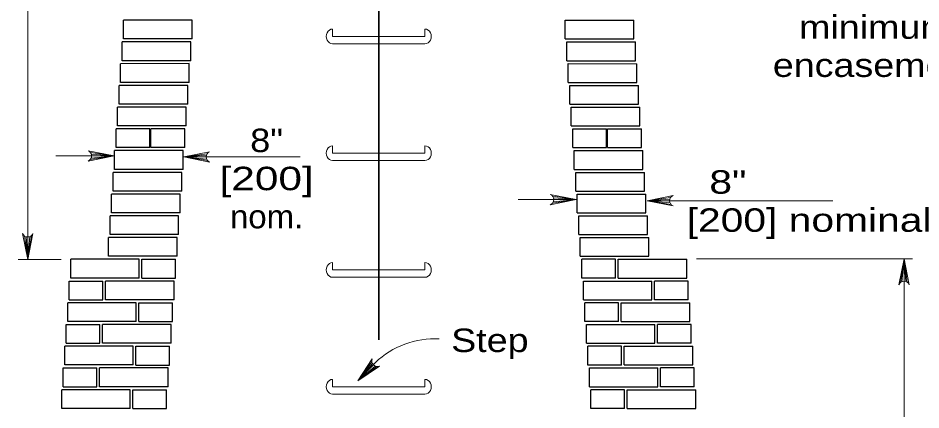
# Model space of a CAD drawing. Extents: x 750.7 to 784.7, y 860.1 to 882.1.
# Drawn here: x 753.86 to 760.02, y 869.85 to 872.53 of the extents above; entities that cross this region are included whole.
import ezdxf
from ezdxf.enums import TextEntityAlignment as Align

# ---------------------------------------------------------------- set-up
doc = ezdxf.new("R2010")
doc.units = 0
doc.header["$LTSCALE"] = 0.064
doc.layers.add('1', color=7, linetype='Continuous', lineweight=13)

msp = doc.modelspace()

# ---------------------------------------------------------------- linework, layer by layer
at = {"layer": '1', "lineweight": 35}
msp.add_line((756.31867, 870.33167), (756.31867, 877.19075), dxfattribs=at)
at = {"layer": '1'}
for p, q in [((753.92483, 870.88017), (753.92483, 873.18092)), ((756.00417, 872.40133), (756.00417, 872.4515)), ((756.63317, 872.40142), (756.63308, 872.4515)), ((756.00417, 872.40133), (756.63317, 872.40142)), ((756.00417, 872.35125), (756.63317, 872.35125)), ((756.00417, 871.60475), (756.00417, 871.65492)), ((756.63317, 871.60483), (756.63308, 871.65492)), ((754.11692, 871.58633), (754.51358, 871.58633)), ((754.35142, 871.5615), (754.51358, 871.58633)), ((754.35325, 871.60875), (754.51358, 871.58633)), ((754.3575, 871.57192), (754.51358, 871.58633)), ((754.35867, 871.59767), (754.51358, 871.58633)), ((754.36033, 871.58633), (754.51358, 871.58633)), ((755.14875, 871.6015), (754.98842, 871.57908)), ((755.14333, 871.59042), (754.98842, 871.57908)), ((754.98842, 871.57908), (755.78258, 871.57908)), ((755.14167, 871.57908), (754.98842, 871.57908)), ((755.1445, 871.56467), (754.98842, 871.57908)), ((755.15067, 871.55433), (754.98842, 871.57908)), ((756.00417, 871.60475), (756.63317, 871.60483)), ((756.00417, 871.55467), (756.63317, 871.55467)), ((757.26908, 871.2885), (757.66575, 871.2885)), ((757.50358, 871.26367), (757.66575, 871.2885)), ((757.50542, 871.31092), (757.66575, 871.2885)), ((757.50967, 871.27408), (757.66575, 871.2885)), ((757.51092, 871.29983), (757.66575, 871.2885)), ((757.5125, 871.2885), (757.66575, 871.2885)), ((758.30917, 871.30308), (758.14883, 871.28067)), ((758.30375, 871.292), (758.14883, 871.28067)), ((758.30208, 871.28067), (758.14883, 871.28067)), ((758.30492, 871.26625), (758.14883, 871.28067)), ((758.31108, 871.25592), (758.14883, 871.28067)), ((758.14883, 871.28067), (759.4165, 871.28067)), ((753.90242, 871.04042), (753.92483, 870.88017)), ((753.9135, 871.035), (753.92483, 870.88017)), ((753.94967, 871.04233), (753.92483, 870.88017)), ((753.93925, 871.03617), (753.92483, 870.88017)), ((753.92483, 871.03333), (753.92483, 870.88017)), ((754.15208, 870.88017), (753.85875, 870.88017)), ((756.00417, 870.80817), (756.00417, 870.85833)), ((756.63317, 870.80817), (756.63308, 870.85833)), ((758.48525, 870.88433), (759.95867, 870.88433)), ((759.87642, 870.72217), (759.90117, 870.88433)), ((759.88675, 870.72833), (759.90117, 870.88433)), ((759.90117, 870.73117), (759.90117, 870.88433)), ((759.9125, 870.7295), (759.90117, 870.88433)), ((759.92358, 870.72408), (759.90117, 870.88433)), ((759.90117, 865.26633), (759.90117, 870.88433)), ((756.00417, 870.80817), (756.63317, 870.80817)), ((756.00417, 870.75808), (756.63317, 870.75808)), ((756.73033, 870.33908), (756.702, 870.33908)), ((756.27142, 870.18108), (756.17533, 870.05083)), ((756.2755, 870.1695), (756.17533, 870.05083)), ((756.2825, 870.16033), (756.17533, 870.05083)), ((756.17533, 870.05083), (756.27408, 870.15508)), ((756.29475, 870.15233), (756.17533, 870.05083)), ((756.3065, 870.14942), (756.17533, 870.05083)), ((756.00417, 870.01158), (756.00417, 870.06175)), ((756.63317, 870.01158), (756.63308, 870.06175)), ((756.00417, 870.01158), (756.63317, 870.01158)), ((756.00417, 869.9615), (756.63317, 869.9615))]:
    msp.add_line(p, q, dxfattribs=at)
at = {"layer": '1', "lineweight": 25}
for p, q in [((754.52742, 871.64258), (754.52742, 871.77067)), ((754.765, 871.64258), (754.765, 871.77067)), ((757.87233, 871.64258), (757.87233, 871.77067)), ((758.10983, 871.64258), (758.10983, 871.77067)), ((754.75758, 871.64258), (754.52742, 871.64258)), ((754.99508, 871.64258), (754.765, 871.64258)), ((757.64217, 871.64258), (757.87233, 871.64258)), ((757.87975, 871.64258), (758.10983, 871.64258)), ((754.93358, 870.753), (754.93358, 870.88108)), ((757.70375, 870.753), (757.70375, 870.88108)), ((754.438, 870.60475), (754.438, 870.73283)), ((754.70342, 870.753), (754.93358, 870.753)), ((757.93383, 870.753), (757.70375, 870.753)), ((758.19925, 870.60475), (758.19925, 870.73283)), ((754.20792, 870.60475), (754.438, 870.60475)), ((754.91308, 870.4565), (754.91308, 870.5845)), ((757.72425, 870.4565), (757.72425, 870.5845)), ((758.42942, 870.60475), (758.19925, 870.60475)), ((754.4175, 870.30825), (754.4175, 870.43625)), ((754.68292, 870.4565), (754.91308, 870.4565)), ((757.95433, 870.4565), (757.72425, 870.4565)), ((758.21975, 870.30825), (758.21975, 870.43625)), ((754.18742, 870.30825), (754.4175, 870.30825)), ((754.89258, 870.15992), (754.89258, 870.288)), ((757.74475, 870.15992), (757.74475, 870.288)), ((758.44992, 870.30825), (758.21975, 870.30825)), ((754.66242, 870.15992), (754.89258, 870.15992)), ((757.97492, 870.15992), (757.74475, 870.15992)), ((754.397, 870.01167), (754.397, 870.13975)), ((758.24033, 870.01167), (758.24033, 870.13975)), ((754.16692, 870.01167), (754.397, 870.01167)), ((754.87208, 869.86342), (754.87208, 869.9915)), ((757.76525, 869.86342), (757.76525, 869.9915)), ((758.47042, 870.01167), (758.24033, 870.01167)), ((754.64192, 869.86342), (754.87208, 869.86342)), ((757.99542, 869.86342), (757.76525, 869.86342))]:
    msp.add_line(p, q, dxfattribs=at)
for points in [[(755.04642, 872.38392), (755.04642, 872.512), (754.57875, 872.512)], [(755.04642, 872.38392), (754.57875, 872.38392), (754.57875, 872.512)], [(757.59092, 872.38392), (757.59092, 872.512), (758.05858, 872.512)], [(757.59092, 872.38392), (758.05858, 872.38392), (758.05858, 872.512)], [(755.03617, 872.23567), (755.03617, 872.36375), (754.5685, 872.36375)], [(755.03617, 872.23567), (754.5685, 872.23567), (754.5685, 872.36375)], [(757.60117, 872.23567), (757.60117, 872.36375), (758.06883, 872.36375)], [(757.60117, 872.23567), (758.06883, 872.23567), (758.06883, 872.36375)], [(757.60117, 872.23567), (757.60117, 872.36375), (758.06883, 872.36375)], [(757.60117, 872.23567), (758.06883, 872.23567), (758.06883, 872.36375)], [(755.02592, 872.08742), (755.02592, 872.2155), (754.55825, 872.21542)], [(755.02592, 872.08742), (754.55825, 872.08742), (754.55825, 872.21542)], [(757.61142, 872.08742), (757.61142, 872.2155), (758.07908, 872.21542)], [(757.61142, 872.08742), (758.07908, 872.08742), (758.07908, 872.21542)], [(755.01567, 871.93917), (755.01567, 872.06717), (754.54792, 872.06717)], [(755.01567, 871.93917), (754.54792, 871.93917), (754.54792, 872.06717)], [(757.62167, 871.93917), (757.62167, 872.06717), (758.08933, 872.06717)], [(757.62167, 871.93917), (758.08933, 871.93917), (758.08933, 872.06717)], [(755.00542, 871.79083), (755.00542, 871.91892), (754.53767, 871.91892)], [(755.00542, 871.79083), (754.53767, 871.79083), (754.53767, 871.91892)], [(757.63192, 871.79083), (757.63192, 871.91892), (758.09958, 871.91892)], [(757.63192, 871.79083), (758.09958, 871.79083), (758.09958, 871.91892)], [(754.75758, 871.64258), (754.75758, 871.77067), (754.52742, 871.77067)], [(754.99508, 871.64258), (754.99508, 871.77067), (754.765, 871.77067)], [(757.64217, 871.64258), (757.64217, 871.77067), (757.87233, 871.77067)], [(757.87975, 871.64258), (757.87975, 871.77067), (758.10983, 871.77067)], [(754.98483, 871.49433), (754.98483, 871.62242), (754.51717, 871.62242)], [(754.98483, 871.49433), (754.51717, 871.49433), (754.51717, 871.62242)], [(757.65242, 871.49433), (757.65242, 871.62242), (758.12008, 871.62242)], [(757.65242, 871.49433), (758.12008, 871.49433), (758.12008, 871.62242)], [(754.97458, 871.34608), (754.97458, 871.47417), (754.50692, 871.47417)], [(754.97458, 871.34608), (754.50692, 871.34608), (754.50692, 871.47417)], [(757.66267, 871.34608), (757.66267, 871.47417), (758.13042, 871.47417)], [(757.66267, 871.34608), (758.13042, 871.34608), (758.13042, 871.47417)], [(754.96433, 871.19783), (754.96433, 871.32583), (754.49667, 871.32583)], [(754.96433, 871.19783), (754.49667, 871.19783), (754.49667, 871.32583)], [(757.67292, 871.19783), (757.67292, 871.32583), (758.14067, 871.32583)], [(757.67292, 871.19783), (758.14067, 871.19783), (758.14067, 871.32583)], [(754.95408, 871.04958), (754.95408, 871.17758), (754.48642, 871.17758)], [(754.95408, 871.04958), (754.48642, 871.04958), (754.48642, 871.17758)], [(757.68325, 871.0495), (757.68325, 871.17758), (758.15092, 871.17758)], [(757.68325, 871.0495), (758.15092, 871.04958), (758.15092, 871.17758)], [(754.94383, 870.90125), (754.94383, 871.02933), (754.47617, 871.02933)], [(754.94383, 870.90125), (754.47617, 870.90125), (754.47617, 871.02933)], [(757.6935, 870.90125), (757.6935, 871.02933), (758.16117, 871.02933)], [(757.6935, 870.90125), (758.16117, 870.90125), (758.16117, 871.02933)], [(754.68583, 870.753), (754.68583, 870.88108), (754.21817, 870.88108)], [(754.68583, 870.753), (754.21817, 870.753), (754.21817, 870.88108)], [(754.70342, 870.753), (754.70342, 870.88108), (754.93358, 870.88108)], [(757.93383, 870.753), (757.93383, 870.88108), (757.70375, 870.88108)], [(757.9515, 870.753), (757.9515, 870.88108), (758.41917, 870.88108)], [(757.9515, 870.753), (758.41917, 870.753), (758.41917, 870.88108)], [(754.20792, 870.60475), (754.20792, 870.73283), (754.438, 870.73283)], [(754.92333, 870.60475), (754.92333, 870.73283), (754.45567, 870.73283)], [(754.92333, 870.60475), (754.45567, 870.60475), (754.45567, 870.73283)], [(757.714, 870.60475), (757.714, 870.73283), (758.18167, 870.73283)], [(757.714, 870.60475), (758.18167, 870.60475), (758.18167, 870.73283)], [(758.42942, 870.60475), (758.42942, 870.73283), (758.19925, 870.73283)], [(754.66533, 870.4565), (754.66533, 870.58458), (754.19767, 870.58458)], [(754.66533, 870.4565), (754.19767, 870.4565), (754.19767, 870.58458)], [(754.68292, 870.4565), (754.68292, 870.5845), (754.91308, 870.5845)], [(757.95433, 870.4565), (757.95433, 870.5845), (757.72425, 870.5845)], [(757.972, 870.4565), (757.972, 870.58458), (758.43967, 870.58458)], [(757.972, 870.4565), (758.43967, 870.4565), (758.43967, 870.58458)], [(754.18742, 870.30825), (754.18742, 870.43625), (754.4175, 870.43625)], [(754.90283, 870.30825), (754.90283, 870.43625), (754.43517, 870.43625)], [(754.90283, 870.30825), (754.43517, 870.30825), (754.43517, 870.43625)], [(757.7345, 870.30825), (757.7345, 870.43625), (758.20217, 870.43625)], [(757.7345, 870.30825), (758.20217, 870.30825), (758.20217, 870.43625)], [(758.44992, 870.30825), (758.44992, 870.43625), (758.21975, 870.43625)], [(754.64483, 870.16), (754.64483, 870.288), (754.17717, 870.288)], [(754.64483, 870.16), (754.17717, 870.16), (754.17717, 870.288)], [(754.66242, 870.15992), (754.66242, 870.288), (754.89258, 870.288)], [(757.97492, 870.15992), (757.97492, 870.288), (757.74475, 870.288)], [(757.9925, 870.16), (757.9925, 870.288), (758.46017, 870.288)], [(757.9925, 870.16), (758.46017, 870.16), (758.46017, 870.288)], [(754.16692, 870.01167), (754.16692, 870.13975), (754.397, 870.13975)], [(754.88233, 870.01167), (754.88233, 870.13975), (754.41458, 870.13975)], [(754.88233, 870.01167), (754.41458, 870.01167), (754.41458, 870.13975)], [(757.755, 870.01167), (757.755, 870.13975), (758.22267, 870.13975)], [(757.755, 870.01167), (758.22267, 870.01167), (758.22267, 870.13975)], [(758.47042, 870.01167), (758.47042, 870.13975), (758.24033, 870.13975)], [(754.62433, 869.86342), (754.62433, 869.9915), (754.15658, 869.9915)], [(754.62433, 869.86342), (754.15658, 869.86342), (754.15658, 869.9915)], [(754.64192, 869.86342), (754.64192, 869.9915), (754.87208, 869.9915)], [(757.99542, 869.86342), (757.99542, 869.9915), (757.76525, 869.9915)], [(758.013, 869.86342), (758.013, 869.9915), (758.48067, 869.9915)], [(758.013, 869.86342), (758.48067, 869.86342), (758.48067, 869.9915)]]:
    msp.add_lwpolyline(points, dxfattribs=at)
at = {"layer": '1'}
for points in [[(754.3365, 871.55092), (754.51358, 871.58633), (754.3365, 871.62175)], [(755.1655, 871.54367), (754.98842, 871.57908), (755.1655, 871.6145)], [(757.48867, 871.25308), (757.66575, 871.2885), (757.48867, 871.32392)], [(758.32592, 871.24525), (758.14883, 871.28067), (758.32592, 871.31608)], [(753.96025, 871.05717), (753.92483, 870.88017), (753.88942, 871.05717)], [(759.86575, 870.70733), (759.90117, 870.88433), (759.93658, 870.70733)], [(756.3245, 870.15267), (756.17533, 870.05083), (756.27383, 870.20217)]]:
    msp.add_lwpolyline(points, dxfattribs=at)
for centre, radius, start, end in [((754.32221, 871.58634), 0.03822, 292.08605, 67.91218), ((755.17983, 871.57914), 0.03822, 112.08782, 247.91395), ((757.47439, 871.28853), 0.03822, 292.08605, 67.91218), ((758.34023, 871.2807), 0.03822, 112.08782, 247.91395), ((753.92481, 871.07151), 0.03822, 202.08782, 337.91395), ((759.90123, 870.693), 0.03822, 22.08782, 157.91395), ((756.70197, 869.7496), 0.58949, 90, 136.54123), ((756.30914, 870.18765), 0.03822, 157.70543, 293.53156)]:
    msp.add_arc(centre, radius, start, end, dxfattribs=at)
for centre, major_axis, end_param in [((756.00413, 872.40137), (0, 0.05012), 3.1415958), ((756.63317, 872.40137), (0, -0.05012), 3.143156), ((756.00413, 871.60479), (0, 0.05012), 3.1415958), ((756.63317, 871.60479), (0, -0.05012), 3.143156), ((756.00413, 870.80821), (0, 0.05012), 3.1415958), ((756.63317, 870.80821), (0, -0.05012), 3.143156), ((756.00413, 870.01162), (0, 0.05012), 3.1415958), ((756.63317, 870.01162), (0, -0.05012), 3.143156)]:
    msp.add_ellipse(centre, major_axis=major_axis, ratio=0.869565, start_param=0.000003, end_param=end_param, dxfattribs=at)

# ---------------------------------------------------------------- texts
for s, width, p in [('minimum', 1.2, (759.70558, 872.38492)), ('encasement', 1.2, (759.70558, 872.12492)), ('8"', 1.15, (755.55396, 871.61225)), ('[200]', 1.35, (755.55404, 871.35225)), ('nom.', 1.05, (755.554, 871.09225))]:
    msp.add_text(s, height=0.16, dxfattribs=dict(at, width=width)).set_placement(p, align=Align.CENTER)
for s, width, p in [('  8"', 1.3, (758.41875, 871.32858)), ('[200] nominal', 1.3, (758.41875, 871.06858)), ('Step', 1.2, (756.81242, 870.24833))]:
    msp.add_text(s, height=0.16, dxfattribs=dict(at, width=width)).set_placement(p)

doc.saveas('drawing.dxf')
